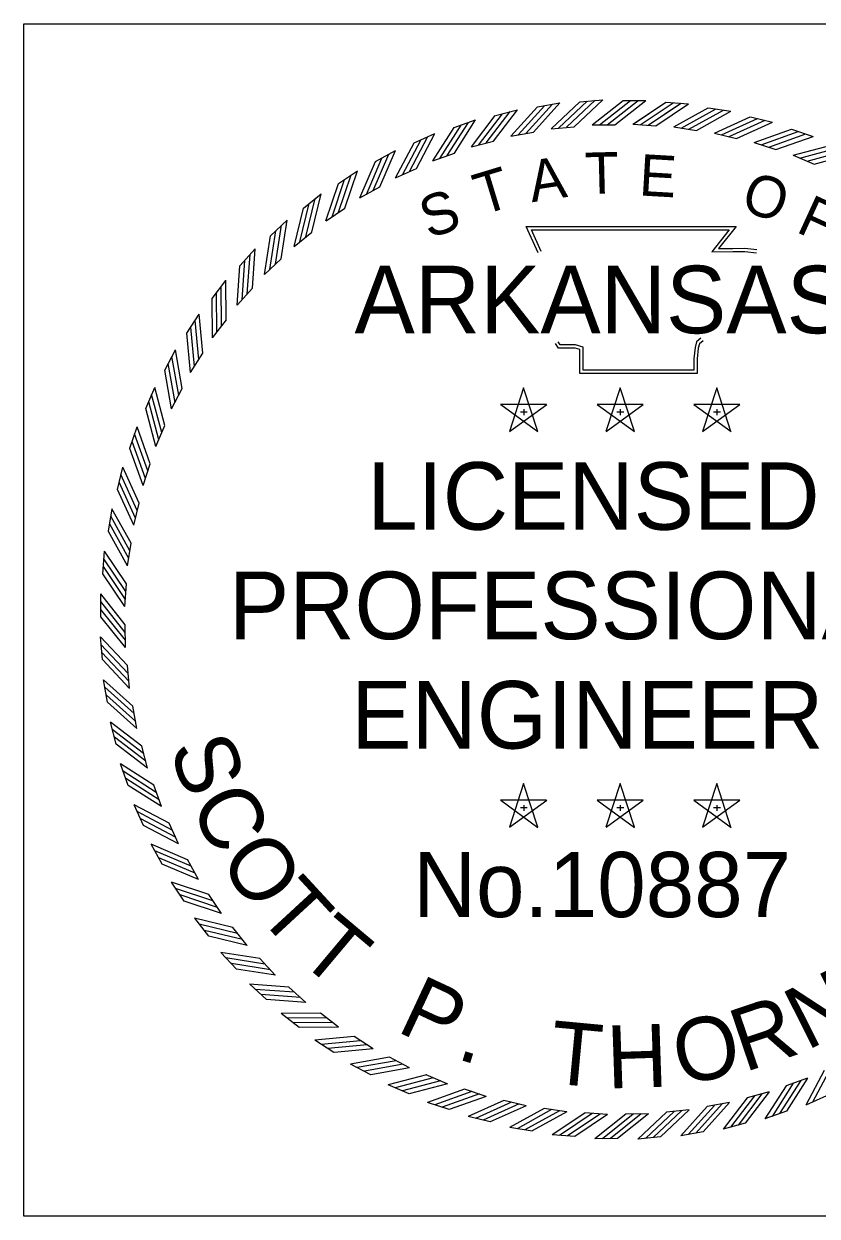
# Model space of a CAD drawing. Extents: x 166 to 3406, y 71 to 2074.
# Drawn here: x 3033.6 to 3217.3, y 386.2 to 662.3 of the extents above; entities that cross this region are included whole.
import ezdxf

# ---------------------------------------------------------------- set-up
doc = ezdxf.new("R2010")
doc.units = 0
doc.layers.add('R_No Plot', color=7, linetype='Continuous')
doc.layers.add('STAMP', color=7, linetype='Continuous')

msp = doc.modelspace()

# ---------------------------------------------------------------- linework, layer by layer
at = {"layer": 'R_No Plot'}
msp.add_lwpolyline([(3033.61, 662.33), (3309.76, 662.33), (3309.76, 386.19), (3033.61, 386.19)], close=True, dxfattribs=at)
at = {"layer": 'STAMP'}
for p, q in [((3152.5, 643.09), (3157.7, 644.01)), ((3162.37, 644.27), (3167.62, 644.76)), ((3172.35, 644.57), (3177.63, 644.57)), ((3182.23, 644.18), (3187.49, 643.79)), ((3182.23, 644.17), (3187.49, 643.78)), ((3142.77, 641.1), (3147.87, 642.44)), ((3192.08, 642.89), (3197.29, 642.07)), ((3201.8, 640.8), (3206.92, 639.56)), ((3133.23, 638.32), (3138.2, 640.07)), ((3155.72, 638.03), (3160.98, 638.51)), ((3165.16, 638.96), (3170.44, 638.96)), ((3174.64, 639.1), (3179.91, 638.72)), ((3174.64, 639.1), (3179.91, 638.72)), ((3184.1, 638.47), (3189.32, 637.65)), ((3211.31, 637.92), (3216.31, 636.25)), ((3123.95, 634.75), (3128.76, 636.91)), ((3137.24, 633.85), (3142.35, 635.19)), ((3146.39, 636.32), (3151.6, 637.24)), ((3193.48, 637.05), (3198.61, 635.8)), ((3115, 630.43), (3119.62, 632.98)), ((3128.32, 630.63), (3133.3, 632.39)), ((3202.71, 634.87), (3207.72, 633.2)), ((3211.73, 631.93), (3216.58, 629.85)), ((3106.44, 625.39), (3110.83, 628.31)), ((3119.69, 626.69), (3124.51, 628.85)), ((3111.42, 622.04), (3116.05, 624.6)), ((3098.32, 619.66), (3102.46, 622.93)), ((3103.57, 616.73), (3107.96, 619.66)), ((3090.71, 613.27), (3094.55, 616.88)), ((3096.18, 610.79), (3100.31, 614.08)), ((3083.65, 606.28), (3087.18, 610.19)), ((3089.3, 604.26), (3093.15, 607.88)), ((3077.19, 598.73), (3080.39, 602.92)), ((3082.99, 597.18), (3086.53, 601.1)), ((3071.37, 590.68), (3074.21, 595.11)), ((3077.28, 589.61), (3080.49, 593.81)), ((3066.24, 582.16), (3068.71, 586.82)), ((3072.22, 581.59), (3075.06, 586.04)), ((3061.83, 573.26), (3063.9, 578.11)), ((3067.83, 573.18), (3070.3, 577.85)), ((3149.32, 578.05), (3146.02, 567.93)), ((3152.6, 567.94), (3149.32, 578.06)), ((3171.68, 578.05), (3168.38, 567.93)), ((3174.96, 567.94), (3171.68, 578.06)), ((3194.04, 578.05), (3190.74, 567.93)), ((3197.32, 567.94), (3194.05, 578.06)), ((3154.63, 574.19), (3143.99, 574.2)), ((3144, 574.19), (3152.6, 567.93)), ((3146.03, 567.94), (3154.65, 574.19)), ((3148.56, 572.49), (3150.14, 572.49)), ((3149.33, 573.06), (3149.33, 571.72)), ((3176.99, 574.19), (3166.35, 574.2)), ((3166.36, 574.19), (3174.97, 567.93)), ((3168.39, 567.94), (3177.01, 574.19)), ((3170.92, 572.49), (3172.5, 572.49)), ((3171.69, 573.06), (3171.69, 571.72)), ((3199.36, 574.19), (3188.71, 574.2)), ((3188.72, 574.19), (3197.33, 567.93)), ((3190.75, 567.94), (3199.37, 574.19)), ((3193.28, 572.49), (3194.86, 572.49)), ((3194.05, 573.06), (3194.05, 571.72)), ((3058.17, 564.02), (3059.84, 569.02)), ((3064.16, 564.44), (3066.24, 569.3)), ((3055.29, 554.51), (3056.53, 559.63)), ((3061.22, 555.42), (3062.89, 560.44)), ((3053.2, 544.8), (3054.02, 550)), ((3059.04, 546.19), (3060.29, 551.33)), ((3057.62, 536.82), (3058.44, 542.04)), ((3051.92, 534.94), (3052.31, 540.2)), ((3051.46, 525.02), (3051.41, 530.29)), ((3056.99, 527.36), (3057.37, 532.62)), ((3057.13, 517.87), (3057.08, 523.16)), ((3051.82, 515.08), (3051.33, 520.33)), ((3058.06, 508.44), (3057.58, 513.7)), ((3053, 505.22), (3052.08, 510.41)), ((3059.77, 499.11), (3058.85, 504.31)), ((3054.99, 495.48), (3053.64, 500.58)), ((3062.24, 489.95), (3060.9, 495.06)), ((3057.77, 485.94), (3056.02, 490.91)), ((3065.46, 481.03), (3063.7, 486.01)), ((3149.32, 486.37), (3146.02, 476.25)), ((3152.6, 476.26), (3149.32, 486.38)), ((3171.68, 486.37), (3168.38, 476.25)), ((3174.96, 476.26), (3171.68, 486.38)), ((3194.04, 486.37), (3190.74, 476.25)), ((3197.32, 476.26), (3194.05, 486.38)), ((3061.34, 476.67), (3059.18, 481.48)), ((3154.63, 482.51), (3143.99, 482.52)), ((3144, 482.51), (3152.6, 476.24)), ((3146.03, 476.26), (3154.65, 482.5)), ((3148.56, 480.81), (3150.14, 480.81)), ((3149.33, 481.37), (3149.33, 480.04)), ((3176.99, 482.51), (3166.35, 482.52)), ((3166.36, 482.51), (3174.97, 476.24)), ((3168.39, 476.26), (3177.01, 482.5)), ((3170.92, 480.81), (3172.5, 480.81)), ((3171.69, 481.37), (3171.69, 480.04)), ((3199.36, 482.51), (3188.71, 482.52)), ((3188.72, 482.51), (3197.33, 476.24)), ((3190.75, 476.26), (3199.37, 482.5)), ((3193.28, 480.81), (3194.86, 480.81)), ((3194.05, 481.37), (3194.05, 480.04)), ((3069.4, 472.41), (3067.24, 477.23)), ((3065.66, 467.72), (3063.1, 472.33)), ((3074.05, 464.14), (3071.49, 468.76)), ((3070.7, 459.16), (3067.78, 463.54)), ((3079.36, 456.28), (3076.43, 460.68)), ((3076.43, 451.04), (3073.16, 455.17)), ((3085.3, 448.89), (3082.01, 453.03)), ((3082.82, 443.42), (3079.21, 447.27)), ((3091.83, 442.01), (3088.21, 445.87)), ((3089.81, 436.36), (3085.9, 439.9)), ((3098.91, 435.7), (3094.98, 439.24)), ((3097.36, 429.9), (3093.17, 433.1)), ((3106.48, 429.99), (3102.28, 433.2)), ((3105.41, 424.08), (3100.97, 426.93)), ((3114.5, 424.93), (3110.05, 427.78)), ((3122.91, 420.55), (3118.24, 423.02)), ((3113.92, 418.95), (3109.27, 421.42)), ((3131.65, 416.87), (3126.79, 418.95)), ((3215.06, 418.17), (3210.08, 416.41)), ((3122.83, 414.54), (3117.98, 416.62)), ((3140.67, 413.93), (3135.65, 415.6)), ((3206.14, 414.95), (3201.03, 413.61)), ((3132.07, 410.88), (3127.07, 412.55)), ((3149.9, 411.75), (3144.76, 413)), ((3196.98, 412.48), (3191.78, 411.57)), ((3219.42, 414.05), (3214.61, 411.89)), ((3141.58, 408), (3136.46, 409.25)), ((3159.27, 410.33), (3154.05, 411.16)), ((3168.73, 409.7), (3163.46, 410.09)), ((3178.22, 409.85), (3172.93, 409.8)), ((3187.65, 410.78), (3182.39, 410.29)), ((3210.15, 410.49), (3205.18, 408.73)), ((3151.29, 405.91), (3146.09, 406.73)), ((3200.61, 407.7), (3195.51, 406.36)), ((3161.15, 404.63), (3155.89, 405.02)), ((3171.07, 404.17), (3165.8, 404.12)), ((3181.01, 404.53), (3175.76, 404.05)), ((3190.87, 405.71), (3185.68, 404.79))]:
    msp.add_line(p, q, dxfattribs=at)
for points in [[(3149.86, 636.95), (3155.97, 643.72)], [(3151.59, 637.24), (3157.7, 644.01)], [(3155.72, 638.02), (3162.36, 644.27)], [(3157.41, 638.16), (3164.05, 644.41)], [(3159.23, 638.37), (3165.87, 644.62)], [(3160.98, 638.51), (3167.62, 644.76)], [(3165.15, 638.95), (3172.35, 644.56)], [(3166.85, 638.94), (3174.04, 644.55)], [(3168.68, 638.98), (3175.87, 644.59)], [(3170.44, 638.96), (3177.63, 644.57)], [(3174.63, 639.1), (3182.22, 644.17)], [(3174.64, 639.1), (3182.22, 644.17)], [(3176.32, 638.96), (3183.92, 644.03)], [(3176.33, 638.96), (3183.91, 644.03)], [(3178.15, 638.87), (3185.75, 643.94)], [(3178.16, 638.87), (3185.74, 643.93)], [(3179.91, 638.72), (3187.5, 643.79)], [(3179.91, 638.72), (3187.49, 643.79)], [(3137.23, 633.84), (3142.76, 641.1)], [(3138.88, 634.26), (3144.41, 641.51)], [(3140.64, 634.76), (3146.17, 642.02)], [(3142.34, 635.19), (3147.87, 642.45)], [(3146.39, 636.31), (3152.5, 643.09)], [(3148.06, 636.59), (3154.17, 643.37)], [(3184.1, 638.46), (3192.07, 642.89)], [(3185.77, 638.19), (3193.75, 642.61)], [(3187.59, 637.94), (3195.56, 642.36)], [(3189.32, 637.65), (3197.3, 642.07)], [(3193.47, 637.05), (3201.79, 640.8)], [(3128.31, 630.62), (3133.22, 638.31)], [(3129.92, 631.17), (3134.83, 638.86)], [(3131.63, 631.82), (3136.54, 639.51)], [(3133.29, 632.39), (3138.2, 640.08)], [(3195.12, 636.63), (3203.43, 640.38)], [(3196.91, 636.24), (3205.22, 639.99)], [(3198.61, 635.81), (3206.93, 639.56)], [(3202.7, 634.87), (3211.3, 637.92)], [(3121.24, 627.36), (3125.5, 635.43)], [(3122.9, 628.15), (3127.16, 636.21)], [(3124.51, 628.85), (3128.76, 636.92)], [(3204.31, 634.32), (3212.9, 637.37)], [(3206.06, 633.78), (3214.65, 636.83)], [(3207.72, 633.21), (3216.31, 636.25)], [(3116.04, 624.6), (3119.62, 632.99)], [(3119.69, 626.68), (3123.95, 634.74)], [(3211.72, 631.93), (3220.54, 634.26)], [(3213.27, 631.25), (3222.09, 633.58)], [(3214.97, 630.56), (3223.79, 632.89)], [(3111.42, 622.04), (3115, 630.43)], [(3112.91, 622.84), (3116.49, 631.23)], [(3114.5, 623.76), (3118.07, 632.15)], [(3216.58, 629.86), (3225.4, 632.19)], [(3106.49, 618.7), (3109.36, 627.36)], [(3107.96, 619.66), (3110.83, 628.32)], [(3103.56, 616.72), (3106.44, 625.38)], [(3104.98, 617.65), (3107.86, 626.31)], [(3098.92, 613), (3101.07, 621.86)], [(3100.31, 614.07), (3102.46, 622.94)], [(3096.17, 610.78), (3098.32, 619.65)], [(3097.51, 611.83), (3099.66, 620.69)], [(3093.15, 607.87), (3094.56, 616.89)], [(3089.3, 604.25), (3090.71, 613.26)], [(3090.55, 605.4), (3091.96, 614.41)], [(3091.85, 606.68), (3093.26, 615.7)], [(3152.71, 609.28), (3149.9, 615.37), (3198.52, 615.4), (3194.46, 610.29), (3197.76, 610.34), (3200.52, 610.37), (3203.28, 610.07)], [(3153.41, 609.61), (3151.11, 614.6), (3196.92, 614.63), (3192.85, 609.5), (3197.77, 609.57), (3200.49, 609.6), (3203.19, 609.31)], [(3084.13, 598.42), (3084.79, 607.52)], [(3085.33, 599.81), (3085.99, 608.91)], [(3086.52, 601.1), (3087.18, 610.2)], [(3082.98, 597.18), (3083.65, 606.27)], [(3080.48, 593.81), (3080.39, 602.93)], [(3078.32, 590.94), (3078.23, 600.06)], [(3079.4, 592.42), (3079.31, 601.54)], [(3077.28, 589.6), (3077.19, 598.72)], [(3075.06, 586.04), (3074.21, 595.12)], [(3073.14, 583), (3072.3, 592.09)], [(3074.1, 584.57), (3073.25, 593.65)], [(3072.22, 581.58), (3071.37, 590.67)], [(3190.86, 588.91), (3190.03, 588.23), (3189.76, 587.23), (3189.48, 584.71), (3189.48, 581.35), (3162.34, 581.35), (3162.34, 585.88), (3162.34, 586.89), (3161.24, 587.23), (3157.38, 587.23), (3156.69, 588.27)], [(3190.37, 589.51), (3189.35, 588.68), (3189, 587.37), (3188.71, 584.75), (3188.71, 582.12), (3163.11, 582.12), (3163.11, 585.88), (3163.11, 587.46), (3161.35, 588), (3157.79, 588), (3157.34, 588.7)], [(3070.3, 577.85), (3068.71, 586.83)], [(3068.64, 574.67), (3067.05, 583.65)], [(3069.46, 576.3), (3067.87, 585.29)], [(3067.83, 573.17), (3066.24, 582.16)], [(3066.23, 569.29), (3063.9, 578.11)], [(3064.84, 565.99), (3062.51, 574.8)], [(3065.53, 567.68), (3063.2, 576.5)], [(3064.16, 564.43), (3061.83, 573.25)], [(3062.88, 560.43), (3059.83, 569.03)], [(3062.31, 558.77), (3059.26, 567.37)], [(3061.22, 555.42), (3058.17, 564.01)], [(3061.77, 557.02), (3058.72, 565.62)], [(3059.85, 549.62), (3056.1, 557.94)], [(3060.28, 551.32), (3056.53, 559.64)], [(3059.46, 547.83), (3055.71, 556.15)], [(3059.04, 546.19), (3055.29, 554.5)], [(3058.44, 542.03), (3054.01, 550.01)], [(3058.15, 540.3), (3053.73, 548.28)], [(3057.62, 536.81), (3053.2, 544.79)], [(3057.9, 538.48), (3053.48, 546.46)], [(3057.37, 532.62), (3052.3, 540.2)], [(3057.13, 529.04), (3052.06, 536.62)], [(3057.22, 530.87), (3052.16, 538.45)], [(3056.99, 527.35), (3051.92, 534.93)], [(3057.08, 523.15), (3051.41, 530.29)], [(3057.08, 521.39), (3051.41, 528.54)], [(3057.14, 519.56), (3051.46, 526.7)], [(3057.14, 517.87), (3051.46, 525.01)], [(3057.58, 513.69), (3051.33, 520.34)], [(3057.72, 511.94), (3051.47, 518.59)], [(3057.93, 510.12), (3051.68, 516.77)], [(3058.07, 508.43), (3051.82, 515.08)], [(3058.85, 504.3), (3052.08, 510.41)], [(3059.14, 502.57), (3052.37, 508.68)], [(3059.5, 500.78), (3052.72, 506.88)], [(3059.78, 499.1), (3053, 505.21)], [(3060.89, 495.05), (3053.64, 500.58)], [(3061.33, 493.35), (3054.07, 498.88)], [(3061.83, 491.59), (3054.58, 497.12)], [(3062.25, 489.95), (3054.99, 495.48)], [(3063.7, 486.01), (3056.01, 490.92)], [(3064.27, 484.34), (3056.58, 489.26)], [(3064.92, 482.63), (3057.23, 487.54)], [(3065.47, 481.03), (3057.78, 485.94)], [(3067.24, 477.22), (3059.17, 481.48)], [(3067.94, 475.61), (3059.88, 479.87)], [(3068.73, 473.96), (3060.66, 478.22)], [(3069.41, 472.4), (3061.35, 476.66)], [(3071.49, 468.75), (3063.1, 472.33)], [(3072.33, 467.21), (3063.93, 470.79)], [(3073.25, 465.63), (3064.86, 469.21)], [(3074.05, 464.13), (3065.66, 467.71)], [(3076.43, 460.67), (3067.77, 463.54)], [(3077.39, 459.2), (3068.73, 462.07)], [(3078.44, 457.7), (3069.78, 460.57)], [(3079.36, 456.28), (3070.71, 459.15)], [(3082.02, 453.02), (3073.15, 455.17)], [(3083.09, 451.64), (3074.23, 453.78)], [(3084.26, 450.23), (3075.4, 452.37)], [(3085.31, 448.89), (3076.44, 451.04)], [(3088.22, 445.86), (3079.2, 447.27)], [(3089.41, 444.57), (3080.39, 445.98)], [(3090.69, 443.26), (3081.68, 444.67)], [(3091.84, 442.01), (3082.82, 443.42)], [(3094.99, 439.23), (3085.89, 439.9)], [(3096.28, 438.05), (3087.18, 438.71)], [(3097.66, 436.85), (3088.57, 437.51)], [(3098.91, 435.7), (3089.82, 436.36)], [(3102.28, 433.19), (3093.16, 433.1)], [(3103.67, 432.11), (3094.55, 432.02)], [(3105.15, 431.03), (3096.03, 430.94)], [(3106.49, 429.99), (3097.37, 429.9)], [(3110.05, 427.77), (3100.97, 426.93)], [(3111.52, 426.81), (3102.44, 425.97)], [(3113.09, 425.86), (3104, 425.01)], [(3114.51, 424.93), (3105.42, 424.08)], [(3118.24, 423.01), (3109.26, 421.42)], [(3119.79, 422.18), (3110.8, 420.58)], [(3121.42, 421.36), (3112.44, 419.76)], [(3122.92, 420.55), (3113.93, 418.95)], [(3218.87, 419.95), (3214.61, 411.88)], [(3220.48, 420.66), (3216.22, 412.59)], [(3126.8, 418.94), (3117.98, 416.62)], [(3128.4, 418.24), (3119.59, 415.91)], [(3130.1, 417.56), (3121.29, 415.23)], [(3211.75, 416.98), (3206.83, 409.29)], [(3213.46, 417.63), (3208.55, 409.94)], [(3215.06, 418.18), (3210.15, 410.49)], [(3131.66, 416.87), (3122.84, 414.55)], [(3135.66, 415.6), (3127.06, 412.55)], [(3137.32, 415.03), (3128.72, 411.98)], [(3139.07, 414.49), (3130.47, 411.44)], [(3204.5, 414.54), (3198.97, 407.29)], [(3206.14, 414.96), (3200.61, 407.71)], [(3210.08, 416.41), (3205.17, 408.72)], [(3140.67, 413.94), (3132.08, 410.89)], [(3144.77, 412.99), (3136.45, 409.25)], [(3146.47, 412.56), (3138.15, 408.81)], [(3148.26, 412.17), (3139.94, 408.42)], [(3149.9, 411.75), (3141.59, 408)], [(3191.79, 411.56), (3185.68, 404.79)], [(3193.52, 411.85), (3187.41, 405.08)], [(3195.31, 412.21), (3189.21, 405.44)], [(3196.99, 412.49), (3190.88, 405.72)], [(3201.04, 413.61), (3195.51, 406.35)], [(3202.74, 414.04), (3197.21, 406.78)], [(3154.06, 411.15), (3146.08, 406.73)], [(3155.79, 410.86), (3147.81, 406.44)], [(3157.61, 410.62), (3149.63, 406.19)], [(3159.28, 410.34), (3151.3, 405.92)], [(3163.47, 410.08), (3155.89, 405.02)], [(3165.22, 409.94), (3157.64, 404.87)], [(3167.05, 409.84), (3159.46, 404.78)], [(3168.74, 409.7), (3161.16, 404.64)], [(3172.94, 409.79), (3165.8, 404.12)], [(3174.7, 409.79), (3167.55, 404.12)], [(3176.53, 409.85), (3169.39, 404.18)], [(3178.22, 409.85), (3171.08, 404.18)], [(3182.4, 410.29), (3175.75, 404.04)], [(3184.15, 410.43), (3177.5, 404.19)], [(3185.97, 410.64), (3179.32, 404.4)], [(3187.66, 410.78), (3181.01, 404.54)]]:
    msp.add_lwpolyline(points, dxfattribs=at)

# ---------------------------------------------------------------- texts
for s, height, rotation, p in [('T', 9.6, 1.4789, (3163.6, 622.88)), ('T', 9.59, 1.4789, (3163.62, 622.9)), ('A', 9.59, 8.6788, (3151.23, 620.99)), ('E', 9.59, 356.672, (3175.89, 622.61)), ('T', 9.59, 16.9015, (3139.59, 617.95)), ('O', 9.59, 341.2218, (3199.18, 619.32)), ('S', 9.59, 19.7726, (3127.39, 612.47)), ('F', 9.59, 335.3628, (3212.1, 614.26)), ('S', 14.57, 289.7007, (3067.13, 494.65)), ('C', 14.57, 296.9967, (3071.81, 481.57)), ('O', 14.57, 304.6575, (3078.48, 468.6)), ('T', 14.57, 312.6831, (3087.24, 456.09)), ('T', 14.57, 319.9791, (3096.66, 445.88)), ('N', 14.57, 26.7376, (3214.85, 424.43)), ('P', 14.57, 334.9359, (3119.6, 429.1)), ('R', 14.57, 18.712, (3200.41, 419.44)), ('T', 14.57, 354.6351, (3154.94, 417.03)), ('O', 14.57, 10.6864, (3185.41, 416.51)), ('H', 14.57, 1.9312, (3168.77, 415.73)), ('.', 14.57, 342.9615, (3133.48, 422.72))]:
    msp.add_text(s, height=height, rotation=rotation, dxfattribs=at).set_placement(p)
for s, height, p in [('ARKANSAS', 15.653, (3110.16, 590.66)), ('LICENSED', 15.653, (3113.14, 545.16)), ('PROFESSIONAL', 15.6526, (3081.09, 519.82)), ('ENGINEER', 15.653, (3109.41, 494.48)), ('No.10887', 15.094, (3123.72, 455.45))]:
    msp.add_text(s, height=height, dxfattribs=at).set_placement(p)

doc.saveas('drawing.dxf')
